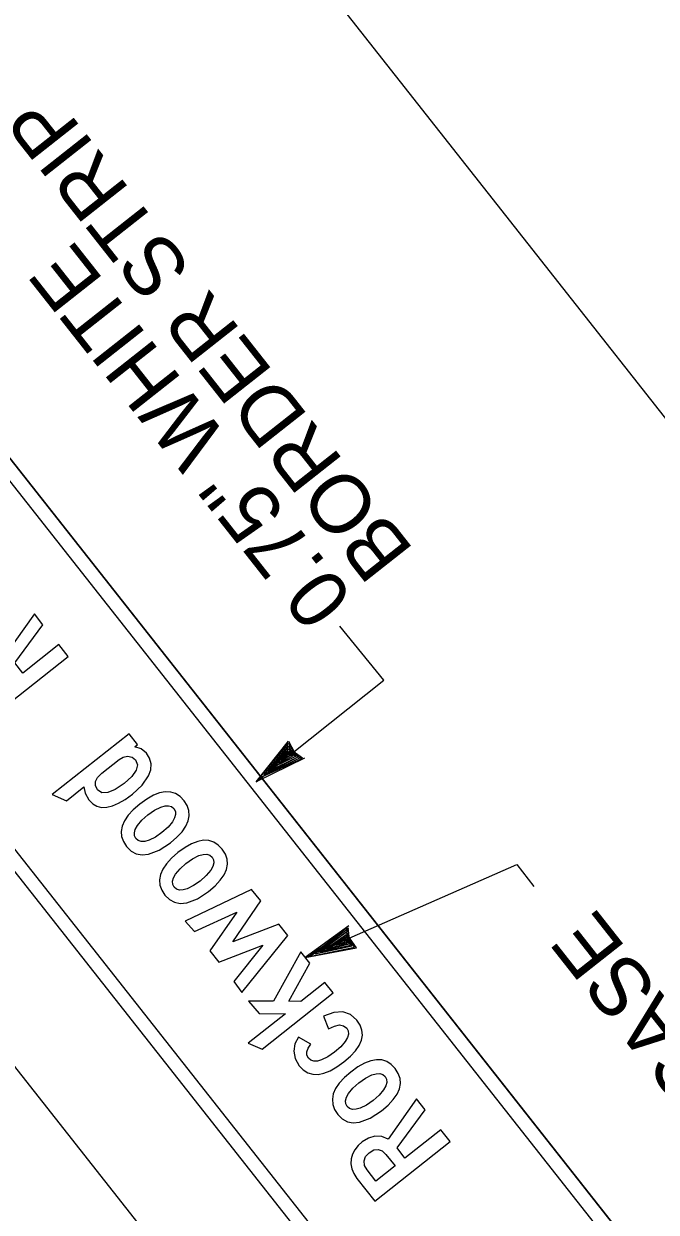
# Model space of a CAD drawing. Extents: x 672438 to 673980, y 1673259 to 1674850.
# Drawn here: x 673782.3 to 673827.5, y 1673411.9 to 1673496.8 of the extents above; entities that cross this region are included whole.
import ezdxf

# ---------------------------------------------------------------- set-up
doc = ezdxf.new("R2010")
doc.units = 0
for name, color, linetype in [('61', 7, 'Continuous'), ('C-ANNO-SYMB', 7, 'Continuous'), ('Level 1', 7, 'Continuous')]:
    doc.layers.add(name, color=color, linetype=linetype)

msp = doc.modelspace()

# ---------------------------------------------------------------- linework, layer by layer
at = {"layer": '61'}
msp.add_lwpolyline([(673971.58, 1673493.353), (673840.538, 1673659.576), (673740.043, 1673580.35), (673871.085, 1673414.127)], close=True, dxfattribs=at)
at = {"layer": 'C-ANNO-SYMB'}
for p, q in [((673826.676, 1673408.211), (673748.669, 1673507.161)), ((673750.527, 1673504.805), (673824.819, 1673410.567)), ((673824.033, 1673409.948), (673749.741, 1673504.186)), ((673734.534, 1673496.017), (673812.54, 1673397.068)), ((673736.391, 1673493.661), (673810.683, 1673399.424)), ((673811.468, 1673400.043), (673737.176, 1673494.28))]:
    msp.add_line(p, q, dxfattribs=at)
for points in [[(673785.482, 1673451.591), (673784.815, 1673452.437), (673782.248, 1673450.413), (673781.681, 1673451.133), (673783.691, 1673453.862), (673783.082, 1673454.635), (673781.042, 1673451.757), (673780.59, 1673451.942), (673780.092, 1673451.962), (673779.633, 1673451.835), (673779.201, 1673451.575), (673778.895, 1673451.297), (673778.659, 1673450.998), (673778.495, 1673450.683), (673778.4, 1673450.352), (673778.381, 1673449.998), (673778.445, 1673449.646), (673778.591, 1673449.297), (673778.819, 1673448.954), (673780.09, 1673447.341), (673785.482, 1673451.591)], [(673790.448, 1673445.3), (673789.844, 1673446.067), (673784.342, 1673441.729), (673785.363, 1673441.292), (673786.612, 1673442.276), (673786.699, 1673441.822), (673786.98, 1673441.35), (673787.247, 1673441.08), (673787.547, 1673440.903), (673787.883, 1673440.816), (673788.252, 1673440.824), (673788.659, 1673440.919), (673789.099, 1673441.109), (673789.575, 1673441.388), (673790.082, 1673441.758), (673790.785, 1673442.411), (673791.235, 1673443.071), (673791.39, 1673443.506), (673791.415, 1673443.923), (673791.314, 1673444.321), (673791.086, 1673444.699), (673790.716, 1673445.008), (673790.259, 1673445.151), (673790.448, 1673445.3)], [(673789.147, 1673444.248), (673789.428, 1673444.408), (673789.734, 1673444.464), (673790.054, 1673444.406), (673790.296, 1673444.211), (673790.438, 1673443.865), (673790.348, 1673443.469), (673790.033, 1673443.026), (673789.486, 1673442.531), (673788.85, 1673442.094), (673788.321, 1673441.871), (673787.904, 1673441.867), (673787.593, 1673442.08), (673787.444, 1673442.369), (673787.444, 1673442.664), (673787.595, 1673442.961), (673787.896, 1673443.262), (673789.147, 1673444.248)], [(673790.606, 1673441.052), (673790.145, 1673440.651), (673789.779, 1673440.256), (673789.516, 1673439.866), (673789.347, 1673439.483), (673789.282, 1673439.106), (673789.312, 1673438.736), (673789.444, 1673438.371), (673789.671, 1673438.015), (673789.993, 1673437.698), (673790.36, 1673437.502), (673790.774, 1673437.427), (673791.232, 1673437.472), (673791.991, 1673437.752), (673792.792, 1673438.279), (673793.263, 1673438.685), (673793.631, 1673439.08), (673793.903, 1673439.469), (673794.072, 1673439.85), (673794.147, 1673440.222), (673794.119, 1673440.588), (673793.993, 1673440.947), (673793.768, 1673441.297), (673793.482, 1673441.594), (673793.163, 1673441.801), (673792.815, 1673441.913), (673792.432, 1673441.93), (673792.024, 1673441.852), (673791.582, 1673441.679), (673791.112, 1673441.413), (673790.606, 1673441.052)], [(673791.176, 1673440.275), (673791.656, 1673440.611), (673792.107, 1673440.84), (673792.412, 1673440.928), (673792.671, 1673440.939), (673792.885, 1673440.872), (673793.049, 1673440.729), (673793.152, 1673440.534), (673793.166, 1673440.312), (673793.1, 1673440.063), (673792.943, 1673439.79), (673792.626, 1673439.406), (673792.191, 1673439.021), (673791.721, 1673438.693), (673791.274, 1673438.475), (673790.974, 1673438.387), (673790.715, 1673438.379), (673790.504, 1673438.446), (673790.337, 1673438.591), (673790.24, 1673438.782), (673790.222, 1673439.001), (673790.29, 1673439.245), (673790.436, 1673439.515), (673790.754, 1673439.896), (673791.176, 1673440.275)], [(673793.337, 1673437.589), (673792.875, 1673437.188), (673792.509, 1673436.793), (673792.247, 1673436.403), (673792.077, 1673436.02), (673792.012, 1673435.643), (673792.042, 1673435.272), (673792.174, 1673434.907), (673792.402, 1673434.551), (673792.723, 1673434.235), (673793.09, 1673434.039), (673793.505, 1673433.964), (673793.962, 1673434.008), (673794.722, 1673434.289), (673795.523, 1673434.816), (673795.993, 1673435.222), (673796.361, 1673435.617), (673796.634, 1673436.005), (673796.802, 1673436.386), (673796.877, 1673436.759), (673796.849, 1673437.125), (673796.723, 1673437.484), (673796.498, 1673437.834), (673796.212, 1673438.131), (673795.893, 1673438.338), (673795.545, 1673438.449), (673795.162, 1673438.467), (673794.755, 1673438.389), (673794.312, 1673438.216), (673793.842, 1673437.95), (673793.337, 1673437.589)], [(673793.906, 1673436.811), (673794.386, 1673437.148), (673794.838, 1673437.377), (673795.142, 1673437.465), (673795.402, 1673437.476), (673795.615, 1673437.409), (673795.78, 1673437.266), (673795.882, 1673437.07), (673795.896, 1673436.848), (673795.83, 1673436.6), (673795.673, 1673436.327), (673795.357, 1673435.943), (673794.922, 1673435.558), (673794.451, 1673435.229), (673794.005, 1673435.012), (673793.704, 1673434.924), (673793.445, 1673434.916), (673793.234, 1673434.983), (673793.067, 1673435.127), (673792.97, 1673435.318), (673792.953, 1673435.538), (673793.021, 1673435.781), (673793.166, 1673436.052), (673793.484, 1673436.433), (673793.906, 1673436.811)], [(673805.688, 1673421.922), (673805.227, 1673421.521), (673804.86, 1673421.126), (673804.598, 1673420.736), (673804.428, 1673420.353), (673804.363, 1673419.976), (673804.393, 1673419.605), (673804.525, 1673419.241), (673804.753, 1673418.884), (673805.074, 1673418.568), (673805.441, 1673418.372), (673805.856, 1673418.297), (673806.314, 1673418.341), (673807.073, 1673418.622), (673807.874, 1673419.149), (673808.344, 1673419.555), (673808.712, 1673419.95), (673808.985, 1673420.338), (673809.153, 1673420.719), (673809.229, 1673421.092), (673809.2, 1673421.458), (673809.074, 1673421.817), (673808.849, 1673422.167), (673808.563, 1673422.464), (673808.244, 1673422.671), (673807.896, 1673422.782), (673807.513, 1673422.8), (673807.106, 1673422.722), (673806.663, 1673422.549), (673806.193, 1673422.283), (673805.688, 1673421.922)], [(673806.257, 1673421.144), (673806.737, 1673421.481), (673807.189, 1673421.71), (673807.493, 1673421.798), (673807.753, 1673421.809), (673807.966, 1673421.742), (673808.131, 1673421.599), (673808.233, 1673421.403), (673808.247, 1673421.181), (673808.181, 1673420.933), (673808.024, 1673420.66), (673807.708, 1673420.276), (673807.273, 1673419.891), (673806.802, 1673419.562), (673806.356, 1673419.345), (673806.055, 1673419.257), (673805.796, 1673419.249), (673805.586, 1673419.316), (673805.418, 1673419.46), (673805.321, 1673419.651), (673805.304, 1673419.871), (673805.372, 1673420.114), (673805.517, 1673420.385), (673805.835, 1673420.766), (673806.257, 1673421.144)], [(673812.784, 1673416.959), (673812.117, 1673417.804), (673809.551, 1673415.781), (673808.983, 1673416.501), (673810.994, 1673419.23), (673810.384, 1673420.003), (673808.344, 1673417.125), (673807.892, 1673417.31), (673807.395, 1673417.33), (673806.935, 1673417.203), (673806.503, 1673416.943), (673806.197, 1673416.665), (673805.961, 1673416.366), (673805.797, 1673416.051), (673805.702, 1673415.72), (673805.684, 1673415.365), (673805.748, 1673415.014), (673805.893, 1673414.665), (673806.121, 1673414.322), (673807.393, 1673412.709), (673812.784, 1673416.959)], [(673808.841, 1673415.221), (673807.466, 1673414.138), (673806.843, 1673414.929), (673806.672, 1673415.244), (673806.636, 1673415.575), (673806.743, 1673415.89), (673806.99, 1673416.162), (673807.325, 1673416.356), (673807.635, 1673416.4), (673807.927, 1673416.295), (673808.196, 1673416.039), (673808.841, 1673415.221)]]:
    msp.add_lwpolyline(points, dxfattribs=at)
for points in [[(673797.89, 1673427.59), (673801.186, 1673431.67), (673800.552, 1673432.475), (673797.249, 1673431.229), (673799.245, 1673434.133), (673798.598, 1673434.954), (673793.861, 1673432.701), (673794.526, 1673431.955), (673797.546, 1673433.347), (673795.611, 1673430.579), (673796.252, 1673429.765), (673799.392, 1673430.97), (673797.337, 1673428.389)], [(673804.42, 1673427.568), (673803.837, 1673428.308), (673802.119, 1673426.954), (673801.26, 1673426.981), (673802.748, 1673429.689), (673802.106, 1673430.504), (673800.157, 1673426.977), (673798.372, 1673426.979), (673799.135, 1673426.109), (673801.016, 1673426.084), (673798.34, 1673423.974), (673799.339, 1673423.563)], [(673804.086, 1673424.995), (673804.516, 1673425.201), (673804.875, 1673425.28), (673805.168, 1673425.227), (673805.393, 1673425.047), (673805.497, 1673424.851), (673805.509, 1673424.631), (673805.439, 1673424.381), (673805.277, 1673424.11), (673804.959, 1673423.725), (673804.526, 1673423.341), (673804.052, 1673423.013), (673803.598, 1673422.795), (673803.299, 1673422.706), (673803.043, 1673422.694), (673802.835, 1673422.758), (673802.669, 1673422.9), (673802.553, 1673423.125), (673802.542, 1673423.367), (673802.637, 1673423.631), (673802.833, 1673423.911), (673801.956, 1673424.412), (673801.682, 1673423.925), (673801.601, 1673423.403), (673801.711, 1673422.876), (673802.002, 1673422.374), (673802.291, 1673422.074), (673802.611, 1673421.873), (673802.963, 1673421.766), (673803.345, 1673421.754), (673803.762, 1673421.836), (673804.207, 1673422.013), (673804.685, 1673422.286), (673805.194, 1673422.653), (673805.651, 1673423.047), (673806.01, 1673423.435), (673806.274, 1673423.817), (673806.437, 1673424.191), (673806.506, 1673424.559), (673806.476, 1673424.921), (673806.349, 1673425.273), (673806.124, 1673425.624), (673805.665, 1673426.036), (673805.115, 1673426.221), (673804.474, 1673426.179), (673803.738, 1673425.913)]]:
    msp.add_lwpolyline(points, close=True, dxfattribs=at)
at = {"layer": 'Level 1'}
for p, q in [((673798.923, 1673442.635), (673801.243, 1673445.545)), ((673799.14, 1673442.871), (673801.224, 1673445.396)), ((673799.492, 1673443.146), (673801.222, 1673445.228)), ((673799.782, 1673443.37), (673801.223, 1673445.096)), ((673801.222, 1673445.228), (673801.36, 1673444.968)), ((673801.223, 1673445.096), (673801.904, 1673444.398)), ((673801.224, 1673445.396), (673801.565, 1673444.831)), ((673801.243, 1673445.545), (673801.635, 1673444.785)), ((673802.383, 1673444.34), (673798.923, 1673442.635)), ((673802.026, 1673444.326), (673799.183, 1673442.902)), ((673802.191, 1673444.288), (673799.343, 1673442.994)), ((673799.71, 1673443.246), (673801.265, 1673444.963)), ((673801.904, 1673444.398), (673799.71, 1673443.246)), ((673801.904, 1673444.398), (673799.782, 1673443.37)), ((673800.216, 1673443.71), (673801.209, 1673444.818)), ((673801.725, 1673444.457), (673800.216, 1673443.71)), ((673800.603, 1673443.979), (673801.174, 1673444.691)), ((673801.563, 1673444.496), (673800.603, 1673443.979)), ((673801.268, 1673444.831), (673800.762, 1673444.073)), ((673800.938, 1673444.274), (673801.204, 1673444.614)), ((673801.455, 1673444.546), (673800.938, 1673444.274)), ((673801.174, 1673444.691), (673801.455, 1673444.546)), ((673801.204, 1673444.614), (673801.286, 1673444.549)), ((673801.209, 1673444.818), (673801.563, 1673444.496)), ((673801.265, 1673444.963), (673801.725, 1673444.457)), ((673801.644, 1673444.56), (673801.268, 1673444.831)), ((673801.286, 1673444.549), (673801.644, 1673444.56)), ((673801.36, 1673444.968), (673801.904, 1673444.398)), ((673801.565, 1673444.831), (673802.236, 1673444.358)), ((673801.635, 1673444.785), (673801.877, 1673444.476)), ((673801.877, 1673444.476), (673802.191, 1673444.288)), ((673802.236, 1673444.358), (673802.017, 1673444.422)), ((673802.017, 1673444.422), (673802.026, 1673444.326)), ((673800.762, 1673444.073), (673800.509, 1673443.972)), ((673805.784, 1673391.741), (673772.9, 1673433.453)), ((673805.542, 1673432.362), (673802.422, 1673430.093)), ((673805.363, 1673432.052), (673802.78, 1673430.198)), ((673805.406, 1673432.217), (673802.936, 1673430.297)), ((673805.371, 1673431.911), (673803.33, 1673430.505)), ((673805.371, 1673431.911), (673803.473, 1673430.511)), ((673805.339, 1673431.726), (673803.975, 1673430.737)), ((673805.298, 1673431.563), (673804.394, 1673430.954)), ((673805.217, 1673431.294), (673805.393, 1673431.605)), ((673805.419, 1673431.101), (673805.298, 1673431.563)), ((673805.572, 1673431.083), (673805.339, 1673431.726)), ((673805.444, 1673432), (673805.363, 1673432.052)), ((673805.621, 1673431.164), (673805.371, 1673431.911)), ((673805.672, 1673430.984), (673805.371, 1673431.911)), ((673805.393, 1673431.605), (673805.457, 1673431.147)), ((673805.426, 1673431.851), (673805.406, 1673432.217)), ((673805.588, 1673431.493), (673805.426, 1673431.851)), ((673805.49, 1673432.224), (673805.444, 1673432)), ((673805.596, 1673431.41), (673805.49, 1673432.224)), ((673802.422, 1673430.093), (673806.077, 1673430.792)), ((673802.732, 1673430.176), (673805.937, 1673430.845)), ((673802.903, 1673430.368), (673803.651, 1673430.877)), ((673803.14, 1673430.358), (673805.787, 1673430.921)), ((673803.651, 1673430.877), (673803.14, 1673430.358)), ((673803.33, 1673430.505), (673805.572, 1673431.083)), ((673803.473, 1673430.511), (673805.672, 1673430.984)), ((673803.868, 1673430.717), (673804.255, 1673431.005)), ((673804.344, 1673430.875), (673803.868, 1673430.717)), ((673803.975, 1673430.737), (673805.419, 1673431.101)), ((673804.551, 1673431.052), (673804.344, 1673430.875)), ((673804.394, 1673430.954), (673805.29, 1673431.129)), ((673805.457, 1673431.147), (673804.551, 1673431.052)), ((673805.292, 1673431.445), (673804.812, 1673431.114)), ((673804.812, 1673431.114), (673805.236, 1673431.191)), ((673805.236, 1673431.191), (673805.217, 1673431.294)), ((673805.29, 1673431.129), (673805.292, 1673431.445)), ((673806.077, 1673430.792), (673805.588, 1673431.493)), ((673805.937, 1673430.845), (673805.596, 1673431.41)), ((673805.787, 1673430.921), (673805.621, 1673431.164)), ((673802.936, 1673430.297), (673802.732, 1673430.176)), ((673802.78, 1673430.198), (673802.903, 1673430.368))]:
    msp.add_line(p, q, dxfattribs=at)
for points in [[(673798.923, 1673442.635), (673808.036, 1673449.895), (673804.898, 1673453.751)], [(673802.422, 1673430.093), (673817.53, 1673436.73), (673818.753, 1673435.179)]]:
    msp.add_lwpolyline(points, dxfattribs=at)

# ---------------------------------------------------------------- texts
for s, p in [('BORDER STRIP', (673810.262, 1673459.148)), ('0.75" WHITE ', (673805.968, 1673455.763)), ('8" UPPERCASE', (673848.674, 1673401.231))]:
    msp.add_text(s, height=4.2, rotation=128.25054, dxfattribs=at).set_placement(p)

doc.saveas('drawing.dxf')
